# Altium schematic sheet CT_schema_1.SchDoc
size 497 x 472 mm
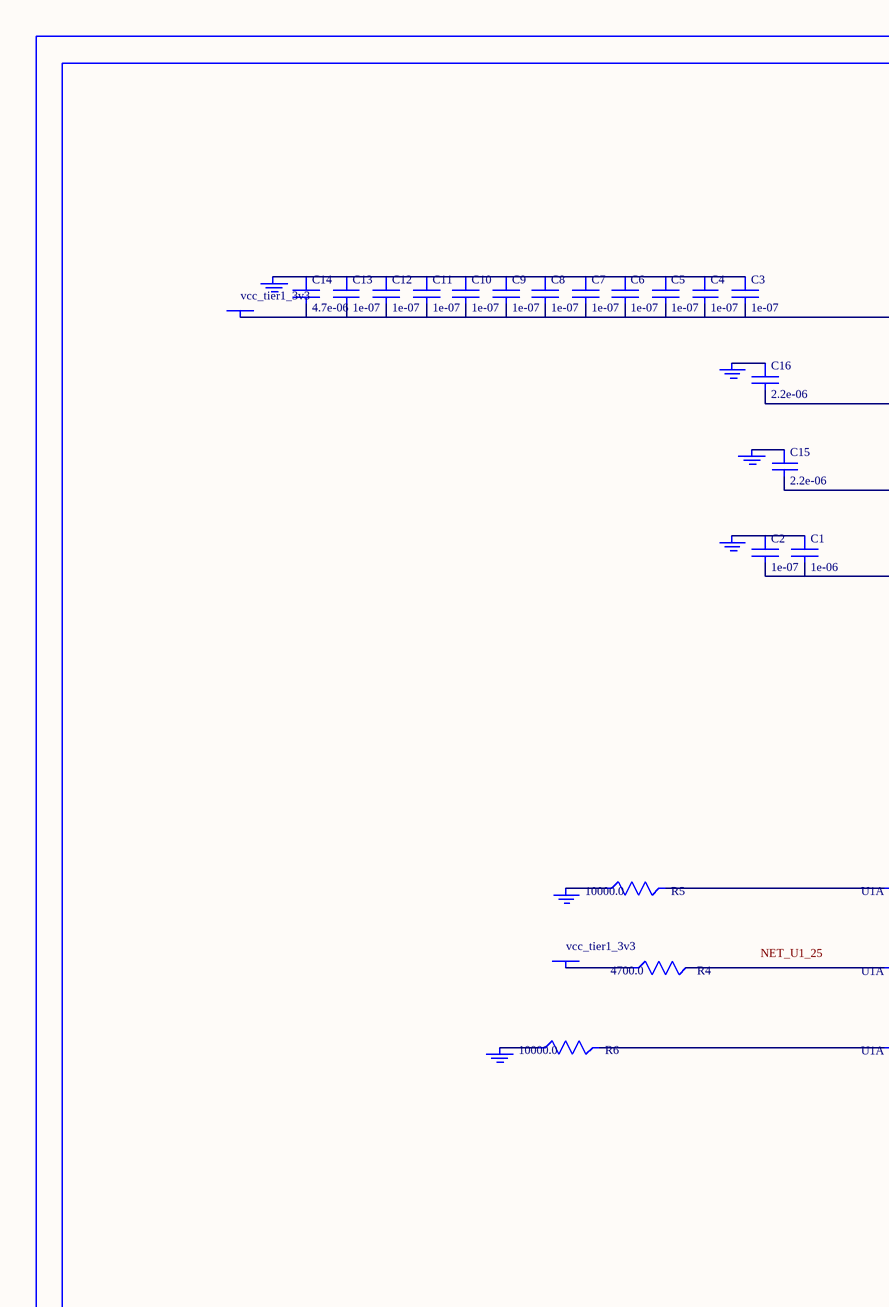
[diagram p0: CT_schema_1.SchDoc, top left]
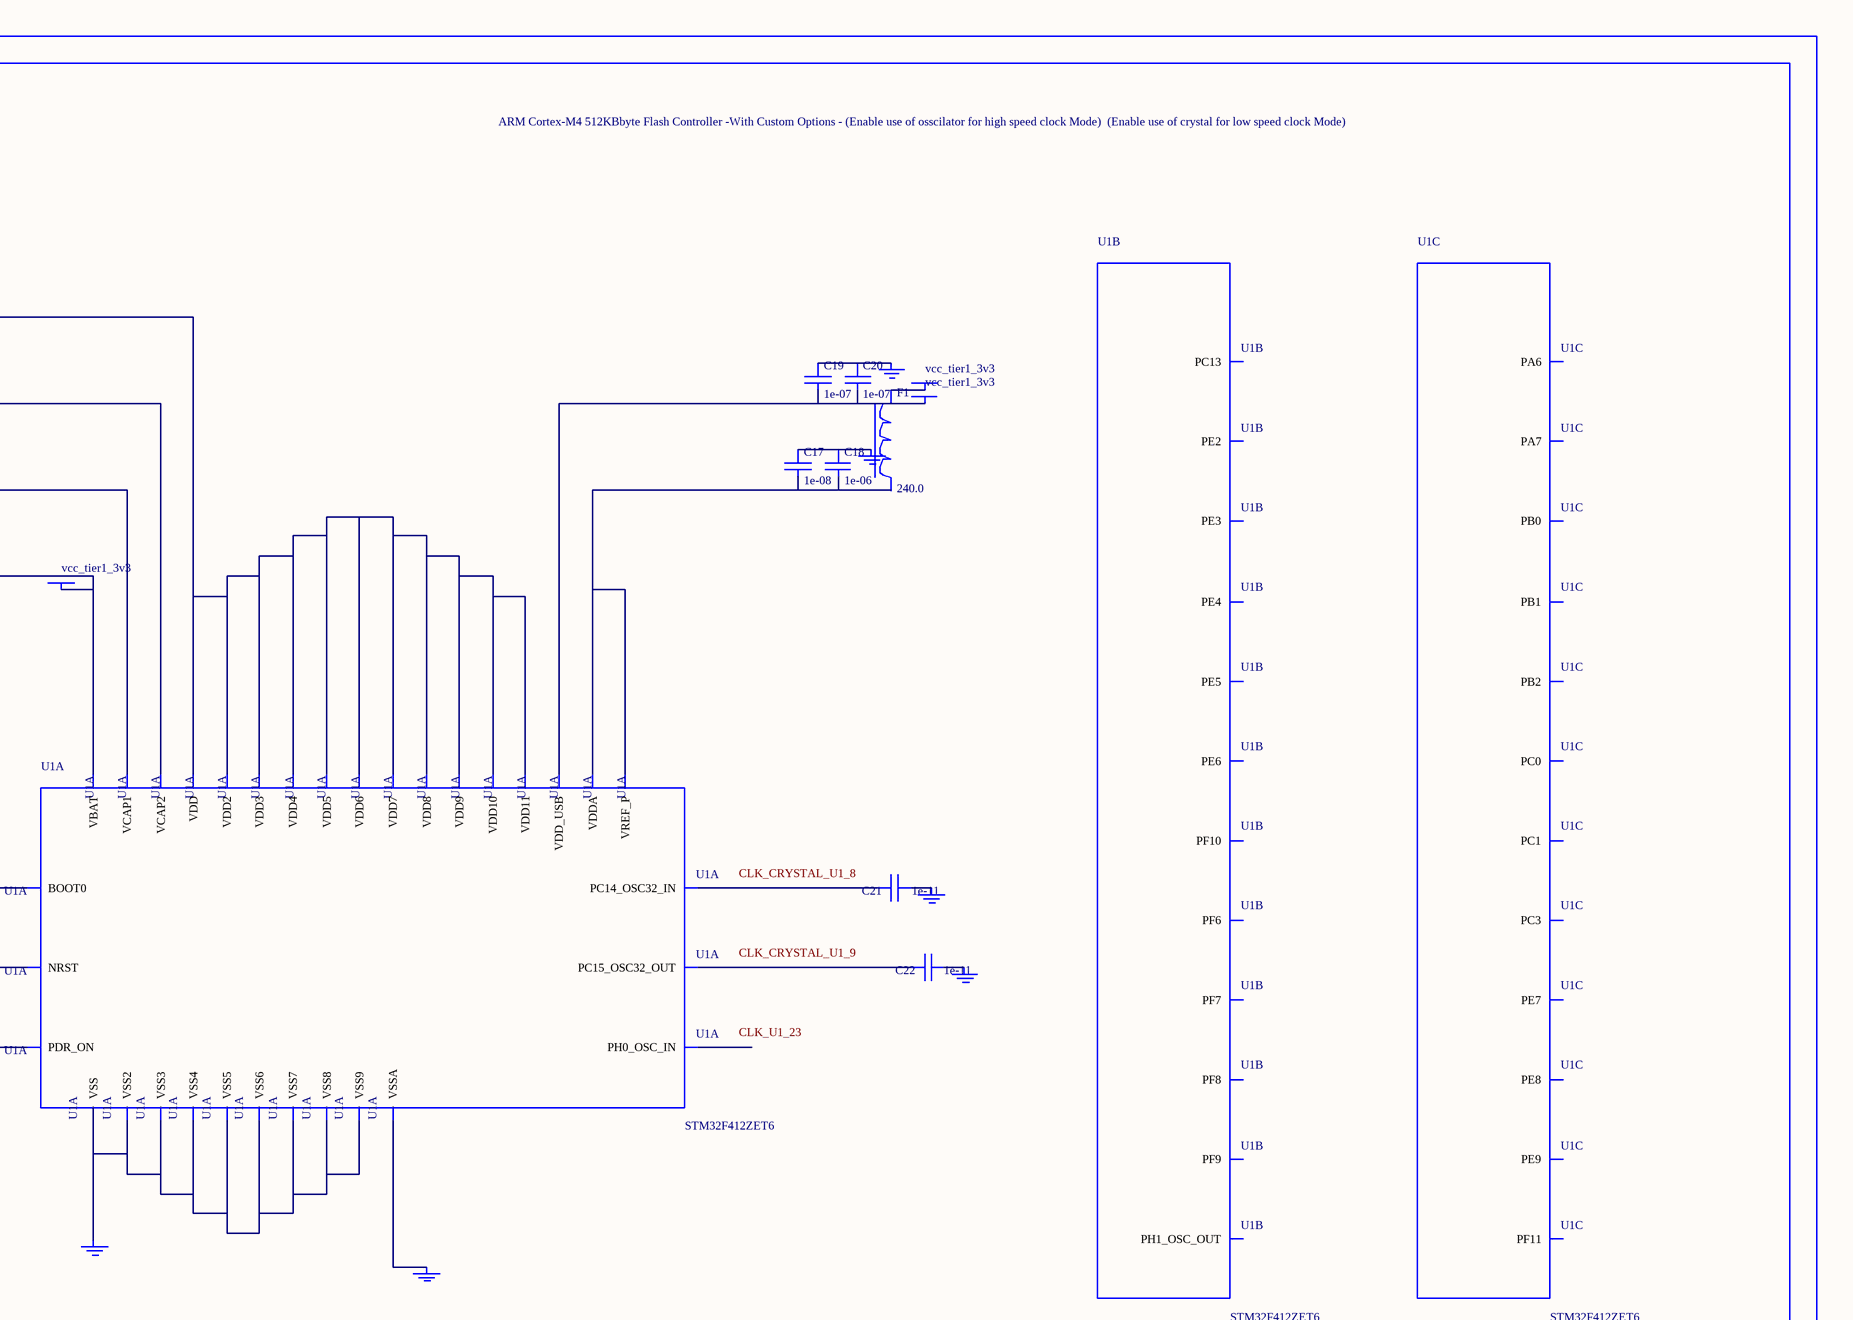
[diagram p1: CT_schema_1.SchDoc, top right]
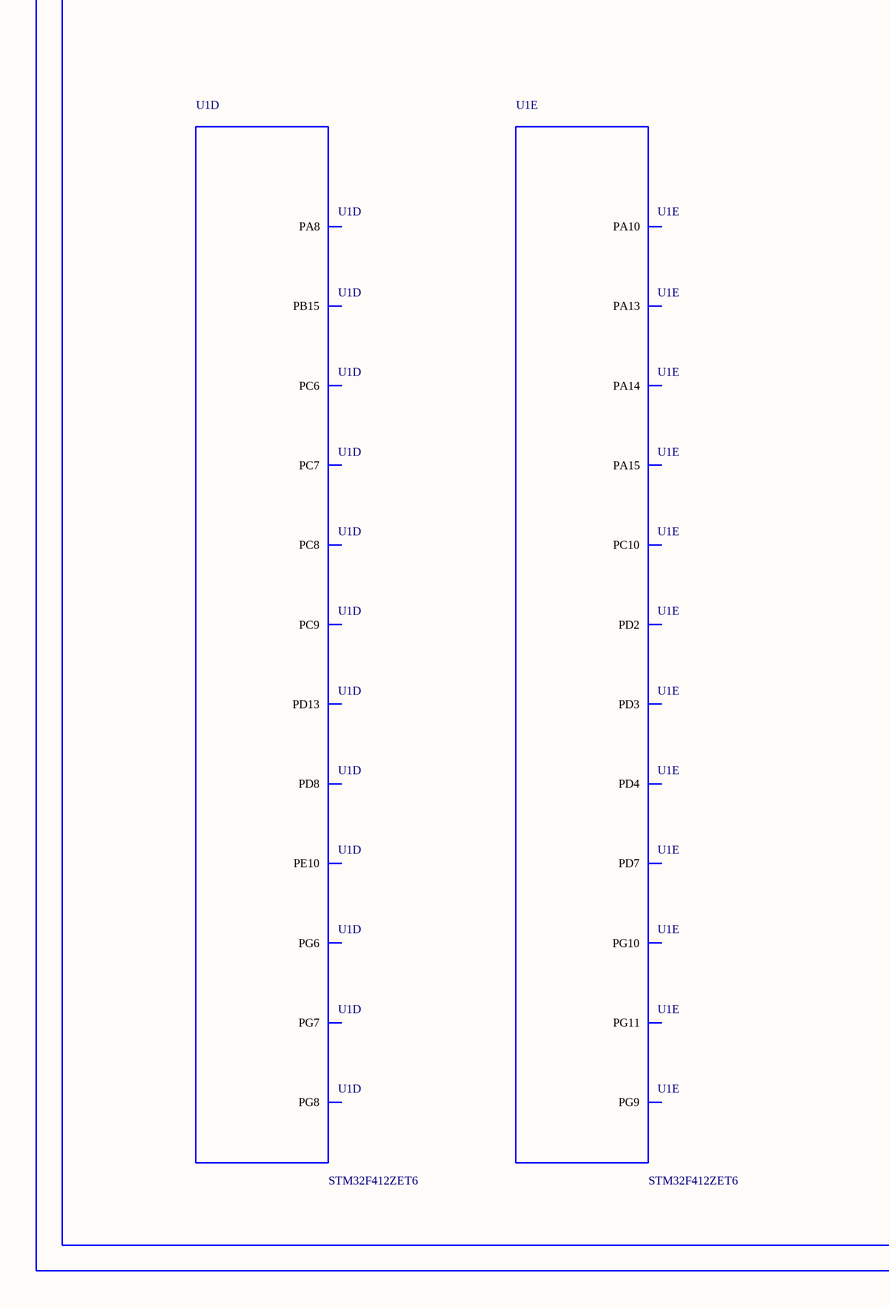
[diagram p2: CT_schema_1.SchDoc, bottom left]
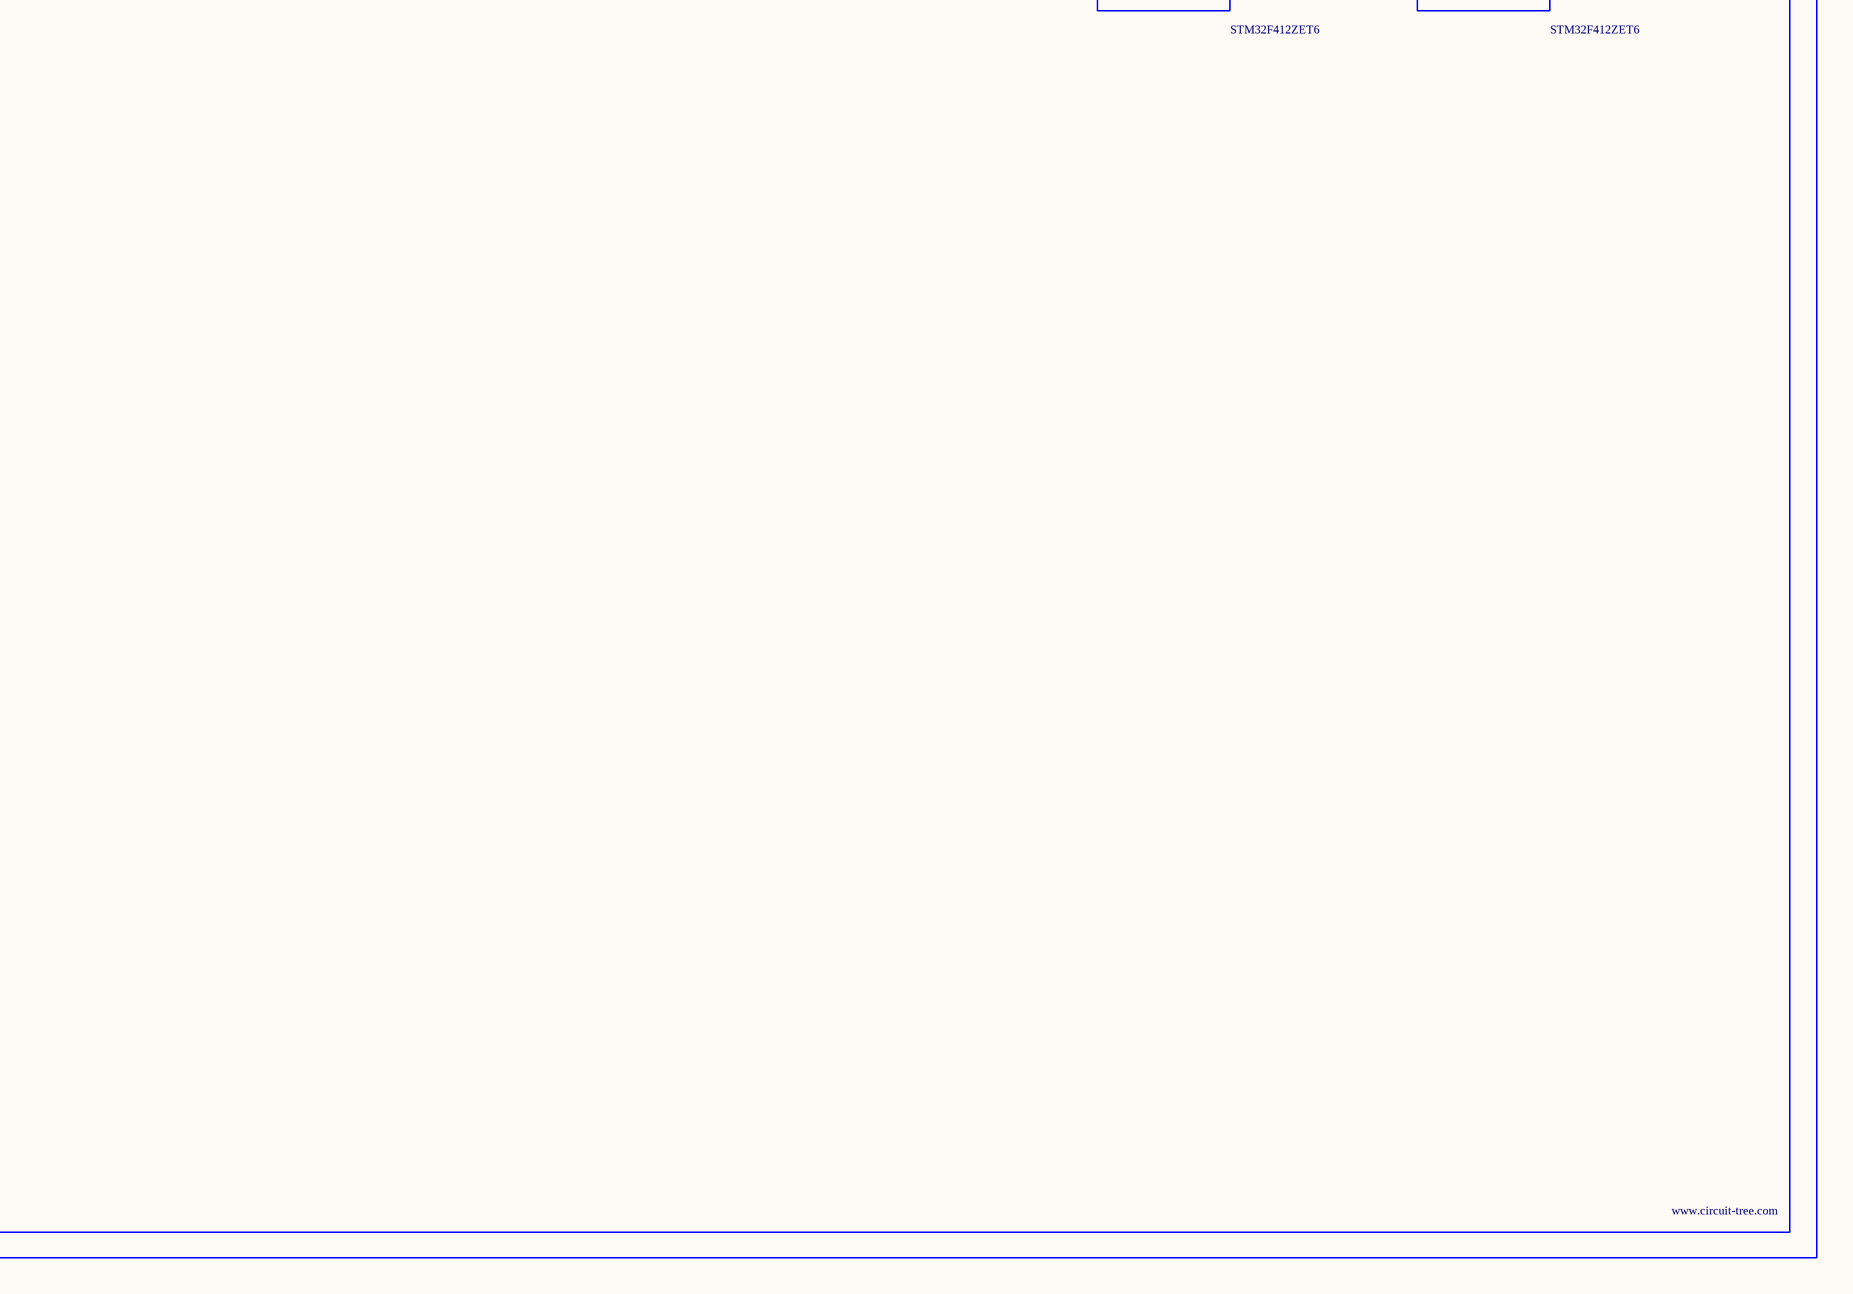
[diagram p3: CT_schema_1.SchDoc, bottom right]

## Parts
BORDER0  (no value)
C1  1e-06  [C0603]
C2  1e-07  [C0603]
C3  1e-07  [C0603]
C4  1e-07  [C0603]
C5  1e-07  [C0603]
C6  1e-07  [C0603]
C7  1e-07  [C0603]
C8  1e-07  [C0603]
C9  1e-07  [C0603]
C10  1e-07  [C0603]
C11  1e-07  [C0603]
C12  1e-07  [C0603]
C13  1e-07  [C0603]
C14  4.7e-06  [C0603]
C15  2.2e-06  [C0603]
C16  2.2e-06  [C0603]
C17  1e-08  [C0603]
C18  1e-06  [C0603]
C19  1e-07  [C0603]
C20  1e-07  [C0402]
C21  1e-11  [C0402]
C22  1e-11  [C0402]
F1  240.0  [L0603]
GND_INSTANCE_0_0  (no value)
GND_INSTANCE_0_1  (no value)
GND_INSTANCE_0_2  (no value)
GND_INSTANCE_0_3  (no value)
GND_INSTANCE_0_4  (no value)
GND_INSTANCE_0_5  (no value)
GND_INSTANCE_0_6  (no value)
GND_INSTANCE_0_7  (no value)
GND_INSTANCE_0_8  (no value)
GND_INSTANCE_0_9  (no value)
GND_INSTANCE_0_10  (no value)
GND_INSTANCE_0_11  (no value)
POWER_INSTANCE_0_0  vcc_tier1_3v3
POWER_INSTANCE_0_1  vcc_tier1_3v3
POWER_INSTANCE_0_2  vcc_tier1_3v3
POWER_INSTANCE_0_3  vcc_tier1_3v3
POWER_INSTANCE_0_4  vcc_tier1_3v3
R4  4700.0  [R0603]
R5  10000.0  [R0603]
R6  10000.0  [R0603]
U1  STM32F412ZET6  [LQFP144]  (parts A,B,C,D,E of 13)

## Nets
NetC1_1: C1.1 C2.1 GND_INSTANCE_0_0.0(GND)
NetC1_2: C1.2 C2.2 POWER_INSTANCE_0_0.0(PWR) U1.6(VBAT)
NetC3_1: C3.1 C4.1 C5.1 C6.1 C7.1 C8.1 C9.1 C10.1 C11.1 C12.1 C13.1 C14.1 GND_INSTANCE_0_3.0(GND)
NetC3_2: C3.2 C4.2 C5.2 C6.2 C7.2 C8.2 C9.2 C10.2 C11.2 C12.2 C13.2 C14.2 POWER_INSTANCE_0_1.0(PWR) U1.17(VDD) U1.30(VDD2) U1.39(VDD3) U1.52(VDD4) U1.62(VDD5) U1.72(VDD6) U1.84(VDD7) U1.108(VDD8) U1.121(VDD9) U1.131(VDD10) U1.144(VDD11)
NetC15_1: C15.1 GND_INSTANCE_0_6.0(GND)
NetC15_2: C15.2 U1.71(VCAP1)
NetC16_1: C16.1 GND_INSTANCE_0_8.0(GND)
NetC16_2: C16.2 U1.106(VCAP2)
NetC17_1: C17.1 C18.1 GND_INSTANCE_0_5.0(GND)
NetC17_2: C17.2 C18.2 U1.32(VREF_P) U1.33(VDDA)
NetC19_1: C19.1 C20.1 GND_INSTANCE_0_7.0(GND)
NetC19_2: C19.2 C20.2 POWER_INSTANCE_0_3.0(PWR) U1.95(VDD_USB)
NetC21_1: C21.1 GND_INSTANCE_0_1.0(GND)
NetC21_2: C21.2 U1.8(PC14_OSC32_IN)
NetC22_1: C22.1 GND_INSTANCE_0_2.0(GND)
NetC22_2: C22.2 U1.9(PC15_OSC32_OUT)
NetF1_1: F1.1 POWER_INSTANCE_0_2.0(PWR)
NetGND_INSTANCE_0_4_0: GND_INSTANCE_0_4.0(GND) U1.31(VSSA)
NetGND_INSTANCE_0_9_0: GND_INSTANCE_0_9.0(GND) R5.1
NetGND_INSTANCE_0_10_0: GND_INSTANCE_0_10.0(GND) R6.1
NetGND_INSTANCE_0_11_0: GND_INSTANCE_0_11.0(GND) U1.16(VSS) U1.38(VSS2) U1.51(VSS3) U1.61(VSS4) U1.83(VSS5) U1.94(VSS6) U1.107(VSS7) U1.120(VSS8) U1.130(VSS9)
NetPOWER_INSTANCE_0_4_0: POWER_INSTANCE_0_4.0(PWR) R4.1
NetR4_2: R4.2 U1.25(NRST)
NetR5_2: R5.2 U1.138(BOOT0)
NetR6_2: R6.2 U1.143(PDR_ON)

Not connected (* = marked no-connect by the designer): F1 2; U1 1(PE2) 2(PE3) 3(PE4) 4(PE5) 5(PE6) 7(PC13) 18(PF6) 19(PF7) 20(PF8) 21(PF9) 22(PF10) 23(PH0_OSC_IN) 24(PH1_OSC_OUT) 26(PC0) 27(PC1) 29(PC3) 42(PA6) 43(PA7) 46(PB0) 47(PB1) 48(PB2) 49(PF11) 58(PE7) 59(PE8) 60(PE9) 63(PE10) 76(PB15) 77(PD8) 82(PD13) 91(PG6) 92(PG7) 93(PG8) 96(PC6) 97(PC7) 98(PC8) 99(PC9) 100(PA8) 102(PA10) 105(PA13) 109(PA14) 110(PA15) 111(PC10) 116(PD2) 117(PD3) 118(PD4) 123(PD7) 124(PG9) 125(PG10) 126(PG11)

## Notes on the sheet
- Labels drawn without touching a wire or pin: CLK_CRYSTAL_U1_8, CLK_CRYSTAL_U1_9, CLK_U1_23, NET_U1_25

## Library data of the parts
BORDER0 = BORDER_PAGE0
C1 C18 = C0603C105K3RACTU
C2-C13 C19 = 06035C104K4Z2A
C14 = GRM188R6YA475KE15D
C15 C16 = C0603C225K8RACTU
C17 = 06035C103K4Z2A
C20 = C0402C104K3RACTU
C21 C22 = C0402C100K3GACTU
F1 = Z0603C241ASMST
GND_INSTANCE_0_0-GND_INSTANCE_0_11 = GND
POWER_INSTANCE_0_0-POWER_INSTANCE_0_4 = PWR
R4 = RC0603JR-074K7L
R5 R6 = RC0603JR-0710KL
